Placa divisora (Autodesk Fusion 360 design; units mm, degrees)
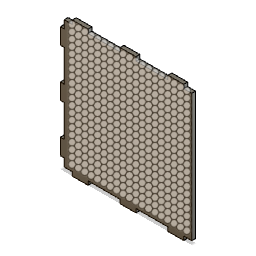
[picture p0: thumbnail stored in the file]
sketch "Sketch1" plane through (0, 0, 0) normal (0, 0, 1) x axis (1, 0, 0)
  line L1 (70, 421.7517) -> (-330, 421.7517)
  line L2 (508.2728, 1021.7517) -> (96.2728, 1021.7517)
  line L3 (508.2728, 421.7517) -> (508.2728, 1021.7517)
  line L4 (96.2728, 421.7517) -> (508.2728, 421.7517)
  line L5 (70, 971.7517) -> (82, 971.7517)
  line L6 (82, 871.7517) -> (70, 871.7517)
  line L7 (70, 821.7517) -> (82, 821.7517)
  line L8 (82, 721.7517) -> (70, 721.7517)
  line L9 (70, 671.7517) -> (82, 671.7517)
  line L10 (82, 571.7517) -> (70, 571.7517)
  line L11 (70, 521.7517) -> (82, 521.7517)
  line L12 (96.2728, 1021.7517) -> (108.2728, 1021.7517)
  line L13 (96.2728, 971.7517) -> (96.2728, 1021.7517)
  line L14 (108.2728, 971.7517) -> (96.2728, 971.7517)
  line L15 (108.2728, 1021.7517) -> (108.2728, 971.7517)
  line L16 (108.2728, 871.7517) -> (108.2728, 821.7517)
  line L17 (108.2728, 821.7517) -> (96.2728, 821.7517)
  line L18 (96.2728, 871.7517) -> (108.2728, 871.7517)
  line L19 (108.2728, 721.7517) -> (108.2728, 671.7517)
  line L20 (108.2728, 671.7517) -> (96.2728, 671.7517)
  line L21 (96.2728, 721.7517) -> (108.2728, 721.7517)
  line L22 (108.2728, 571.7517) -> (108.2728, 521.7517)
  line L23 (108.2728, 521.7517) -> (96.2728, 521.7517)
  line L24 (96.2728, 571.7517) -> (108.2728, 571.7517)
  line L25 (-342, 821.7517) -> (-330, 821.7517)
  line L26 (-342, 521.7517) -> (-330, 521.7517)
  line L27 (-330, 571.7517) -> (-342, 571.7517)
  line L28 (-342, 671.7517) -> (-330, 671.7517)
  line L29 (-330, 721.7517) -> (-342, 721.7517)
  line L30 (-330, 871.7517) -> (-342, 871.7517)
  line L31 (-330, 871.7517) -> (-330, 971.7517)
  line L32 (-330, 721.7517) -> (-330, 821.7517)
  line L33 (-330, 571.7517) -> (-330, 671.7517)
  line L34 (-330, 421.7517) -> (-330, 521.7517)
  line L35 (70, 521.7517) -> (70, 421.7517)
  line L36 (70, 671.7517) -> (70, 571.7517)
  line L37 (70, 821.7517) -> (70, 721.7517)
  line L38 (70, 971.7517) -> (70, 871.7517)
  line L39 (96.2728, 1021.7517) -> (96.2728, 421.7517)
  line L40 (-155, 441.7517) -> (-105, 441.7517)
  line L41 (-155, 453.7517) -> (-155, 441.7517)
  line L42 (-105, 453.7517) -> (-155, 453.7517)
  line L43 (-105, 441.7517) -> (-105, 453.7517)
  line L44 (45, 441.7517) -> (45, 453.7517)
  line L45 (-5, 441.7517) -> (45, 441.7517)
  line L46 (45, 453.7517) -> (-5, 453.7517)
  line L47 (-5, 453.7517) -> (-5, 441.7517)
  line L48 (-255, 441.7517) -> (-255, 453.7517)
  line L49 (-305, 441.7517) -> (-255, 441.7517)
  line L50 (-255, 453.7517) -> (-305, 453.7517)
  line L51 (-305, 453.7517) -> (-305, 441.7517)
  line L52 (283.2728, 453.7517) -> (283.2728, 441.7517)
  line L53 (333.2728, 453.7517) -> (283.2728, 453.7517)
  line L54 (333.2728, 441.7517) -> (333.2728, 453.7517)
  line L55 (333.2728, 441.7517) -> (283.2728, 441.7517)
  line L56 (483.2728, 453.7517) -> (433.2728, 453.7517)
  line L57 (433.2728, 453.7517) -> (433.2728, 441.7517)
  line L58 (483.2728, 441.7517) -> (433.2728, 441.7517)
  line L59 (483.2728, 441.7517) -> (483.2728, 453.7517)
  line L60 (183.2728, 453.7517) -> (133.2728, 453.7517)
  line L61 (133.2728, 453.7517) -> (133.2728, 441.7517)
  line L62 (183.2728, 441.7517) -> (133.2728, 441.7517)
  line L63 (183.2728, 441.7517) -> (183.2728, 453.7517)
  line L64 (-342, 971.7517) -> (-330, 971.7517)
  line L65 (82, 1021.7517) -> (-342, 1021.7517)
  line L66 (-255, 1021.7517) -> (-305, 1021.7517)
  line L67 (-255, 1009.7517) -> (-255, 1021.7517)
  line L68 (-305, 1009.7517) -> (-255, 1009.7517)
  line L69 (-305, 1021.7517) -> (-305, 1009.7517)
  line L70 (-105, 1021.7517) -> (-155, 1021.7517)
  line L71 (-105, 1009.7517) -> (-105, 1021.7517)
  line L72 (-155, 1009.7517) -> (-105, 1009.7517)
  line L73 (-155, 1021.7517) -> (-155, 1009.7517)
  line L74 (45, 1021.7517) -> (-5, 1021.7517)
  line L75 (45, 1009.7517) -> (45, 1021.7517)
  line L76 (-5, 1009.7517) -> (45, 1009.7517)
  line L77 (-5, 1021.7517) -> (-5, 1009.7517)
  line L78 (183.2728, 1021.7517) -> (133.2728, 1021.7517)
  line L79 (183.2728, 1009.7517) -> (183.2728, 1021.7517)
  line L80 (133.2728, 1009.7517) -> (183.2728, 1009.7517)
  line L81 (133.2728, 1021.7517) -> (133.2728, 1009.7517)
  line L82 (333.2728, 1021.7517) -> (283.2728, 1021.7517)
  line L83 (333.2728, 1009.7517) -> (333.2728, 1021.7517)
  line L84 (283.2728, 1009.7517) -> (333.2728, 1009.7517)
  line L85 (283.2728, 1021.7517) -> (283.2728, 1009.7517)
  line L86 (483.2728, 1021.7517) -> (433.2728, 1021.7517)
  line L87 (483.2728, 1009.7517) -> (483.2728, 1021.7517)
  line L88 (433.2728, 1009.7517) -> (483.2728, 1009.7517)
  line L89 (433.2728, 1021.7517) -> (433.2728, 1009.7517)
  line L90 (-353.2483, 1448.6304) -> (-751.2483, 1448.6304)
  line L91 (-353.2483, 1050.6304) -> (-353.2483, 1448.6304)
  line L92 (-751.2483, 1050.6304) -> (-353.2483, 1050.6304)
  line L93 (-751.2483, 1448.6304) -> (-751.2483, 1050.6304)
  line L94 (516.9867, 1469.9076) -> (118.9867, 1469.9076)
  line L95 (516.9867, 1569.9076) -> (516.9867, 1469.9076)
  line L96 (118.9867, 1569.9076) -> (516.9867, 1569.9076)
  line L97 (118.9867, 1469.9076) -> (118.9867, 1569.9076)
  line L98 (-869.8125, 1189.3882) -> (-769.8125, 1189.3882)
  line L99 (-869.8125, 1563.3882) -> (-869.8125, 1189.3882)
  line L100 (-769.8125, 1563.3882) -> (-869.8125, 1563.3882)
  line L101 (-769.8125, 1189.3882) -> (-769.8125, 1563.3882)
  line L102 (-725.5452, 1469.0357) -> (-725.5452, 1569.0357)
  line L103 (-351.5452, 1469.0357) -> (-725.5452, 1469.0357)
  line L104 (-351.5452, 1569.0357) -> (-351.5452, 1469.0357)
  line L105 (-725.5452, 1569.0357) -> (-351.5452, 1569.0357)
  line L106 (70.2483, 1569.9076) -> (-327.7517, 1569.9076)
  line L107 (70.2483, 1469.9076) -> (70.2483, 1569.9076)
  line L108 (-327.7517, 1469.9076) -> (70.2483, 1469.9076)
  line L109 (-327.7517, 1569.9076) -> (-327.7517, 1469.9076)
  line L110 (1885.2395, 210.7799) -> (1885.2395, -187.2201)
  line L111 (2283.2395, -187.2201) -> (2283.2395, 210.7799)
  line L112 (2283.2395, 210.7799) -> (1885.2395, 210.7799)
  line L113 (1885.2395, -187.2201) -> (2283.2395, -187.2201)
  line L114 (-342, 521.7517) -> (-342, 571.7517)
  line L115 (-342, 671.7517) -> (-342, 721.7517)
  line L116 (-342, 971.7517) -> (-342, 1021.7517)
  line L117 (-342, 821.7517) -> (-342, 871.7517)
  line L118 (82, 521.7517) -> (82, 571.7517)
  line L119 (82, 671.7517) -> (82, 721.7517)
  line L120 (82, 971.7517) -> (82, 1021.7517)
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  point P55 (-305, 1021.7517)
  point P59 (-155, 1021.7517)
  point P63 (-5, 1021.7517)
  point P67 (133.2728, 1021.7517)
  point P71 (283.2728, 1021.7517)
  point P75 (433.2728, 1021.7517)
  point P39 (-305, 453.7517)
  point P79 (-305, 453.7517)
  point P24 (-330, 521.7517)
  point P80 (-330, 521.7517)
  point P23 (-330, 571.7517)
  point P81 (-330, 571.7517)
  point P26 (-330, 671.7517)
  point P82 (-330, 671.7517)
  point P42 (-255, 453.7517)
  point P83 (-255, 453.7517)
  point P41 (-305, 441.7517)
  point P84 (-305, 441.7517)
  point P40 (-255, 441.7517)
  point P85 (-255, 441.7517)
  point P32 (-155, 441.7517)
  point P86 (-155, 441.7517)
  point P33 (-155, 453.7517)
  point P87 (-155, 453.7517)
  point P34 (-105, 453.7517)
  point P88 (-105, 453.7517)
  point P31 (-105, 441.7517)
  point P89 (-105, 441.7517)
  point P35 (-5, 453.7517)
  point P90 (-5, 453.7517)
  point P38 (45, 453.7517)
  point P91 (45, 453.7517)
  point P36 (45, 441.7517)
  point P92 (45, 441.7517)
  point P37 (-5, 441.7517)
  point P93 (-5, 441.7517)
  point P12 (70, 521.7517)
  point P94 (70, 521.7517)
  point P13 (70, 571.7517)
  point P95 (70, 571.7517)
  point P10 (70, 671.7517)
  point P96 (70, 671.7517)
  point P27 (-330, 721.7517)
  point P97 (-330, 721.7517)
  point P11 (70, 721.7517)
  point P98 (70, 721.7517)
  point P8 (70, 821.7517)
  point P99 (70, 821.7517)
  point P9 (70, 871.7517)
  point P100 (70, 871.7517)
  point P25 (-330, 871.7517)
  point P101 (-330, 871.7517)
  point P29 (-330, 821.7517)
  point P102 (-330, 821.7517)
  point P28 (-330, 971.7517)
  point P103 (-330, 971.7517)
  point P58 (-305, 1009.7517)
  point P104 (-305, 1009.7517)
  point P57 (-255, 1009.7517)
  point P105 (-255, 1009.7517)
  point P62 (-155, 1009.7517)
  point P106 (-155, 1009.7517)
  point P61 (-105, 1009.7517)
  point P107 (-105, 1009.7517)
  point P66 (-5, 1009.7517)
  point P108 (-5, 1009.7517)
  point P65 (45, 1009.7517)
  point P109 (45, 1009.7517)
  point P7 (70, 971.7517)
  point P110 (70, 971.7517)
  point P70 (133.2728, 1009.7517)
  point P111 (133.2728, 1009.7517)
  point P69 (183.2728, 1009.7517)
  point P112 (183.2728, 1009.7517)
  point P74 (283.2728, 1009.7517)
  point P113 (283.2728, 1009.7517)
  point P73 (333.2728, 1009.7517)
  point P114 (333.2728, 1009.7517)
  point P78 (433.2728, 1009.7517)
  point P115 (433.2728, 1009.7517)
  point P77 (483.2728, 1009.7517)
  point P116 (483.2728, 1009.7517)
  point P16 (108.2728, 971.7517)
  point P117 (108.2728, 971.7517)
  point P18 (108.2728, 871.7517)
  point P118 (108.2728, 871.7517)
  point P17 (108.2728, 821.7517)
  point P119 (108.2728, 821.7517)
  point P20 (108.2728, 721.7517)
  point P120 (108.2728, 721.7517)
  point P19 (108.2728, 671.7517)
  point P121 (108.2728, 671.7517)
  point P22 (108.2728, 571.7517)
  point P122 (108.2728, 571.7517)
  point P21 (108.2728, 521.7517)
  point P123 (108.2728, 521.7517)
  point P52 (133.2728, 453.7517)
  point P124 (133.2728, 453.7517)
  point P53 (133.2728, 441.7517)
  point P125 (133.2728, 441.7517)
  point P51 (183.2728, 441.7517)
  point P126 (183.2728, 441.7517)
  point P54 (183.2728, 453.7517)
  point P127 (183.2728, 453.7517)
  point P45 (283.2728, 453.7517)
  point P128 (283.2728, 453.7517)
  point P44 (283.2728, 441.7517)
  point P129 (283.2728, 441.7517)
  point P43 (333.2728, 441.7517)
  point P130 (333.2728, 441.7517)
  point P46 (333.2728, 453.7517)
  point P131 (333.2728, 453.7517)
  point P48 (433.2728, 453.7517)
  point P132 (433.2728, 453.7517)
  point P50 (483.2728, 453.7517)
  point P133 (483.2728, 453.7517)
  point P47 (483.2728, 441.7517)
  point P134 (483.2728, 441.7517)
  point P49 (433.2728, 441.7517)
  point P135 (433.2728, 441.7517)
  point P585 (-342, 571.7517)
  point P587 (-342, 721.7517)
  point P589 (-342, 871.7517)
  point P593 (82, 571.7517)
  point P595 (82, 721.7517)
  point P597 (82, 871.7517)
  point P599 (96.2728, 871.7517)
  point P600 (96.2728, 821.7517)
  point P601 (96.2728, 721.7517)
  point P602 (96.2728, 671.7517)
  point P603 (96.2728, 571.7517)
  point P604 (96.2728, 521.7517)
  point P2 (-330, 421.7517)
  point P3 (70, 421.7517)
  point P6 (108.2728, 1021.7517)
  point P56 (-255, 1021.7517)
  point P60 (-105, 1021.7517)
  point P190 (-751.2483, 1448.6304)
  point P191 (-353.2483, 1448.6304)
  point P193 (-751.2483, 1050.6304)
  point P194 (118.9867, 1469.9076)
  point P195 (516.9867, 1469.9076)
  point P197 (118.9867, 1569.9076)
  point P198 (-769.8125, 1189.3882)
  point P199 (-869.8125, 1189.3882)
  point P201 (-769.8125, 1563.3882)
  point P202 (-725.5452, 1569.0357)
  point P203 (-725.5452, 1469.0357)
  point P205 (-351.5452, 1569.0357)
  point P206 (-327.7517, 1569.9076)
  point P209 (-327.7517, 1469.9076)
  point P210 (2283.2395, 210.7799)
  point P212 (1885.2395, 210.7799)
  point P213 (1885.2395, -187.2201)
  point P810 (483.2728, 1032.4869)
  point P813 (483.2728, 1044.4869)
  point P811 (433.2728, 1032.4869)
  point P814 (333.2728, 1032.4869)
  point P815 (283.2728, 1032.4869)
  point P817 (333.2728, 1044.4869)
  point P818 (183.2728, 1032.4869)
  point P821 (183.2728, 1044.4869)
  point P819 (133.2728, 1032.4869)
  point P822 (483.2728, 1456.4869)
  point P823 (433.2728, 1456.4869)
  point P825 (483.2728, 1444.4869)
  point P826 (333.2728, 1456.4869)
  point P827 (283.2728, 1456.4869)
  point P829 (333.2728, 1444.4869)
  point P830 (183.2728, 1456.4869)
  point P831 (133.2728, 1456.4869)
  point P833 (183.2728, 1444.4869)
  point P835 (108.2728, 1044.4869)
  point P838 (108.2728, 1069.4869)
  point P841 (108.2728, 1119.4869)
  point P839 (96.2728, 1069.4869)
  point P842 (108.2728, 1219.4869)
  point P843 (96.2728, 1219.4869)
  point P845 (108.2728, 1269.4869)
  point P846 (108.2728, 1369.4869)
  point P849 (108.2728, 1419.4869)
  point P847 (96.2728, 1369.4869)
  horizontal L1
  vertical L35
  vertical L31
  horizontal L2
  vertical L3
  horizontal L4
  horizontal L5
  horizontal L6
  horizontal L7
  horizontal L8
  horizontal L9
  horizontal L10
  horizontal L11
  horizontal L12
  vertical L13
  horizontal L14
  vertical L15
  horizontal L18
  horizontal L17
  vertical L16
  horizontal L21
  horizontal L20
  vertical L19
  horizontal L24
  horizontal L23
  vertical L22
  horizontal L30
  horizontal L25
  horizontal L29
  horizontal L28
  horizontal L27
  horizontal L26
  collinear L31 L32
  collinear L32 L33
  collinear L33 L34
  collinear L35 L36
  collinear L36 L37
  collinear L37 L38
  perpendicular L12 L39
  horizontal L40
  vertical L41
  horizontal L42
  vertical L43
  horizontal L45
  vertical L47
  horizontal L46
  vertical L44
  horizontal L49
  vertical L51
  horizontal L50
  vertical L48
  vertical L52
  horizontal L53
  vertical L54
  perpendicular L54 L55
  vertical L57
  horizontal L56
  vertical L59
  perpendicular L58 L59
  vertical L61
  horizontal L60
  vertical L63
  perpendicular L62 L63
  horizontal L66
  vertical L67
  horizontal L68
  vertical L69
  coincident L65 P55
  horizontal L70
  vertical L71
  horizontal L72
  vertical L73
  coincident L65 P59
  horizontal L74
  vertical L75
  horizontal L76
  vertical L77
  coincident L65 P63
  horizontal L78
  vertical L79
  horizontal L80
  vertical L81
  coincident L2 P67
  horizontal L82
  vertical L83
  horizontal L84
  vertical L85
  coincident L2 P71
  horizontal L86
  vertical L87
  horizontal L88
  vertical L89
  coincident L2 P75
  coincident P39 P79
  coincident P24 P80
  coincident P23 P81
  coincident P26 P82
  coincident P42 P83
  coincident P41 P84
  coincident P40 P85
  coincident P32 P86
  coincident P33 P87
  coincident P34 P88
  coincident P31 P89
  coincident P35 P90
  coincident P38 P91
  coincident P36 P92
  coincident P37 P93
  coincident P12 P94
  coincident P13 P95
  coincident P10 P96
  coincident P27 P97
  coincident P11 P98
  coincident P8 P99
  coincident P9 P100
  coincident P25 P101
  coincident P29 P102
  coincident P28 P103
  coincident P58 P104
  coincident P57 P105
  coincident P62 P106
  coincident P61 P107
  coincident P66 P108
  coincident P65 P109
  coincident P7 P110
  coincident P70 P111
  coincident P69 P112
  coincident P74 P113
  coincident P73 P114
  coincident P78 P115
  coincident P77 P116
  coincident P16 P117
  coincident P18 P118
  coincident P17 P119
  coincident P20 P120
  coincident P19 P121
  coincident P22 P122
  coincident P21 P123
  coincident P52 P124
  coincident P53 P125
  coincident P51 P126
  coincident P54 P127
  coincident P45 P128
  coincident P44 P129
  coincident P43 P130
  coincident P46 P131
  coincident P48 P132
  coincident P50 P133
  coincident P47 P134
  coincident P49 P135
  horizontal L90
  horizontal L92
  vertical L93
  vertical L95
  horizontal L96
  vertical L97
  horizontal L106
  vertical L107
  vertical L109
  horizontal L112
  vertical L111
  horizontal L113
  vertical L110
  perpendicular L1 L116
  coincident P585 L116
  collinear L114 L116
  coincident P587 L116
  collinear L115 L116
  coincident P589 L116
  collinear L116 L117
  perpendicular L1 L120
  coincident P593 L120
  collinear L118 L120
  coincident P595 L120
  collinear L119 L120
  coincident P597 L120
  coincident L39 P599
  coincident L39 P600
  coincident L39 P601
  coincident L39 P602
  coincident L39 P603
  coincident L39 P604
  dimension "d3" distance P2 P3 = 400
  dimension "d6" distance L2 L4 = 600
  dimension "d12" distance P8 P9 = 50
  dimension "d14" distance P10 P11 = 50
  dimension "d16" distance P12 P13 = 50
  dimension "d20" distance P6 P16 = 50
  dimension "d22" distance P17 P18 = 50
  dimension "d24" distance P19 P20 = 50
  dimension "d26" distance P21 P22 = 50
  dimension "d58" distance P31 P32 = 50
  dimension "d59" distance P31 P34 = 12
  dimension "d60" distance P36 P37 = 50
  dimension "d61" distance P36 P38 = 12
  dimension "d62" distance L43 L47 = 100
  dimension "d63" distance P40 P41 = 50
  dimension "d64" distance P40 P42 = 12
  dimension "d65" distance L41 L48 = 100
  dimension "d77" distance P43 P44 = 50
  dimension "d78" distance P43 P46 = 12
  dimension "d79" distance P47 P49 = 50
  dimension "d80" distance P47 P50 = 12
  dimension "d81" distance P51 P53 = 50
  dimension "d82" distance P51 P54 = 12
  dimension "d96" distance P55 P56 = 50
  dimension "d97" distance P55 P58 = 12
  dimension "d98" distance P59 P60 = 50
  dimension "d99" distance P59 P62 = 12
  dimension "d101" distance P63 P66 = 12
  dimension "d103" distance P67 P70 = 12
  dimension "d105" distance P71 P74 = 12
  dimension "d106" distance P75 P78 = 12
  dimension "d133" distance P190 P191 = 398
  dimension "d134" distance P190 P193 = 398
  dimension "d135" distance P194 P195 = 398
  dimension "d136" distance P194 P197 = 100
  dimension "d137" distance P198 P199 = 100
  dimension "d138" distance P198 P201 = 374
  dimension "d139" distance P202 P203 = 100
  dimension "d140" distance P202 P205 = 374
  dimension "d142" distance P206 P209 = 100
  dimension "d143" distance P210 P212 = 398
  dimension "d144" distance P212 P213 = 398
  dimension "d171" diameter = 6.4
  dimension "d172" diameter = 6.4
  dimension "d173" diameter = 6.4
  dimension "d174" diameter = 6.4
  dimension "d175" diameter = 6.4
  dimension "d176" diameter = 6.4
  dimension "d177" diameter = 6.4
  dimension "d178" diameter = 6.4
  dimension "d179" diameter = 6.4
  dimension "d180" diameter = 6.4
  dimension "d181" diameter = 6.4
  dimension "d182" diameter = 6.4
  dimension "d183" diameter = 6.4
  dimension "d184" diameter = 6.4
  dimension "d185" diameter = 6.4
  dimension "d186" diameter = 6.4
  dimension "d187" diameter = 6.4
  dimension "d188" diameter = 6.4
  dimension "d189" diameter = 6.4
  dimension "d190" diameter = 6.4
  dimension "d191" diameter = 6.4
  dimension "d192" diameter = 6.4
  dimension "d193" diameter = 6.4
  dimension "d194" diameter = 6.4
  dimension "d195" diameter = 6.4
  dimension "d196" diameter = 6.4
  dimension "d197" diameter = 6.4
  dimension "d198" diameter = 6.4
  dimension "d199" diameter = 6.4
  dimension "d200" diameter = 6.4
  dimension "d201" diameter = 6.4
  dimension "d202" diameter = 6.4
  dimension "d203" diameter = 6.4
  dimension "d204" diameter = 6.4
  dimension "d205" diameter = 6.4
  dimension "d206" diameter = 6.4
  dimension "d207" diameter = 6.4
  dimension "d208" diameter = 6.4
  dimension "d209" diameter = 6.4
  dimension "d210" diameter = 6.4
  dimension "d211" diameter = 6.4
  dimension "d212" diameter = 6.4
  dimension "d213" diameter = 6.4
  dimension "d214" diameter = 6.4
  dimension "d215" diameter = 6.4
  dimension "d216" diameter = 6.4
  dimension "d217" diameter = 6.4
  dimension "d218" diameter = 6.4
  dimension "d219" diameter = 6.4
  dimension "d220" diameter = 6.4
  dimension "d221" diameter = 6.4
  dimension "d222" diameter = 6.4
  dimension "d223" diameter = 6.4
  dimension "d224" diameter = 6.4
  dimension "d225" diameter = 6.4
  dimension "d226" diameter = 6.4
  dimension "d227" diameter = 6.4
  dimension "d228" diameter = 6.4
  dimension "d230" distance L3 L39 = 412
  dimension "d290" distance P810 P813 = 12
  dimension "d291" distance P810 P811 = 50
  dimension "d292" distance P814 P815 = 50
  dimension "d293" distance P814 P817 = 12
  dimension "d294" distance P818 P821 = 12
  dimension "d295" distance P818 P819 = 50
  dimension "d296" distance P822 P823 = 50
  dimension "d297" distance P822 P825 = 12
  dimension "d298" distance P826 P827 = 50
  dimension "d299" distance P826 P829 = 12
  dimension "d300" distance P830 P831 = 50
  dimension "d301" distance P830 P833 = 12
  dimension "d302" distance P835 P838 = 25
  dimension "d303" distance P838 P841 = 50
  dimension "d304" distance P838 P839 = 12
  dimension "d305" distance L71 L77 = 100
  dimension "d306" distance P841 P842 = 100
  dimension "d307" distance P842 P843 = 12
  dimension "d308" distance P842 P845 = 50
  dimension "d309" distance P845 P846 = 100
  dimension "d310" distance P846 P849 = 50
  dimension "d311" distance P846 P847 = 12
extrude "Extrude7" new body sketch "Sketch1" along normal blind 12
sketch "Sketch4" plane through (0, 0, 12) normal (0, 0, 1) x axis (1, 0, 0)
  line L1 (108.2728, 1369.4869) -> (96.2728, 1369.4869)
  line L2 (108.2728, 1269.4869) -> (108.2728, 1369.4869)
  line L3 (96.2728, 1269.4869) -> (108.2728, 1269.4869)
  line L4 (96.2728, 1219.4869) -> (96.2728, 1269.4869)
  line L5 (108.2728, 1219.4869) -> (96.2728, 1219.4869)
  line L6 (108.2728, 1119.4869) -> (108.2728, 1219.4869)
  line L7 (96.2728, 1119.4869) -> (108.2728, 1119.4869)
  line L8 (96.2728, 1069.4869) -> (96.2728, 1119.4869)
  line L9 (108.2728, 1069.4869) -> (96.2728, 1069.4869)
  line L10 (108.2728, 1044.4869) -> (108.2728, 1069.4869)
  line L11 (133.2728, 1044.4869) -> (108.2728, 1044.4869)
  line L12 (133.2728, 1032.4869) -> (133.2728, 1044.4869)
  line L13 (183.2728, 1032.4869) -> (133.2728, 1032.4869)
  line L14 (183.2728, 1044.4869) -> (183.2728, 1032.4869)
  line L15 (283.2728, 1044.4869) -> (183.2728, 1044.4869)
  line L16 (283.2728, 1032.4869) -> (283.2728, 1044.4869)
  line L17 (333.2728, 1032.4869) -> (283.2728, 1032.4869)
  line L18 (333.2728, 1044.4869) -> (333.2728, 1032.4869)
  line L19 (433.2728, 1044.4869) -> (333.2728, 1044.4869)
  line L20 (433.2728, 1032.4869) -> (433.2728, 1044.4869)
  line L21 (483.2728, 1032.4869) -> (433.2728, 1032.4869)
  line L22 (483.2728, 1044.4869) -> (483.2728, 1032.4869)
  line L23 (508.2728, 1044.4869) -> (483.2728, 1044.4869)
  line L24 (508.2728, 1444.4869) -> (508.2728, 1044.4869)
  line L25 (483.2728, 1444.4869) -> (508.2728, 1444.4869)
  line L26 (483.2728, 1456.4869) -> (483.2728, 1444.4869)
  line L27 (433.2728, 1456.4869) -> (483.2728, 1456.4869)
  line L28 (433.2728, 1444.4869) -> (433.2728, 1456.4869)
  line L29 (333.2728, 1444.4869) -> (433.2728, 1444.4869)
  line L30 (333.2728, 1456.4869) -> (333.2728, 1444.4869)
  line L31 (283.2728, 1456.4869) -> (333.2728, 1456.4869)
  line L32 (283.2728, 1444.4869) -> (283.2728, 1456.4869)
  line L33 (183.2728, 1444.4869) -> (283.2728, 1444.4869)
  line L34 (183.2728, 1456.4869) -> (183.2728, 1444.4869)
  line L35 (133.2728, 1456.4869) -> (183.2728, 1456.4869)
  line L36 (133.2728, 1444.4869) -> (133.2728, 1456.4869)
  line L37 (108.2728, 1444.4869) -> (133.2728, 1444.4869)
  line L38 (108.2728, 1419.4869) -> (108.2728, 1444.4869)
  line L39 (96.2728, 1419.4869) -> (108.2728, 1419.4869)
  line L40 (96.2728, 1369.4869) -> (96.2728, 1419.4869)
sketch "Sketch2" plane through (0, 0, 0) normal (0, 0, 1) x axis (1, 0, 0)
